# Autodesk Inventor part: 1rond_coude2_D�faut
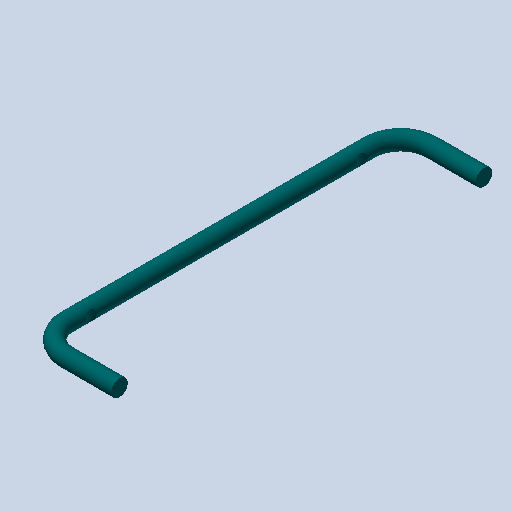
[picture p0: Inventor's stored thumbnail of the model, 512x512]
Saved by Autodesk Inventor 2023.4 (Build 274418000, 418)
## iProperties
Created: 2011-01
Part Number: 1rond_coude2_D�faut
Document SubType Name: Modeling
Designer: eric
Density: 1 g/cm^3
Mass: 12.1463 g
Surface Area: 61.8573 cm^2
Volume: 12.1463 cm^3
Material: Générique
Appearance: 0,128,128
Author: eric
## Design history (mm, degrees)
feature "Base1"
node "Corps solides"
node "Corps surfaciques"
node "Solide1"
